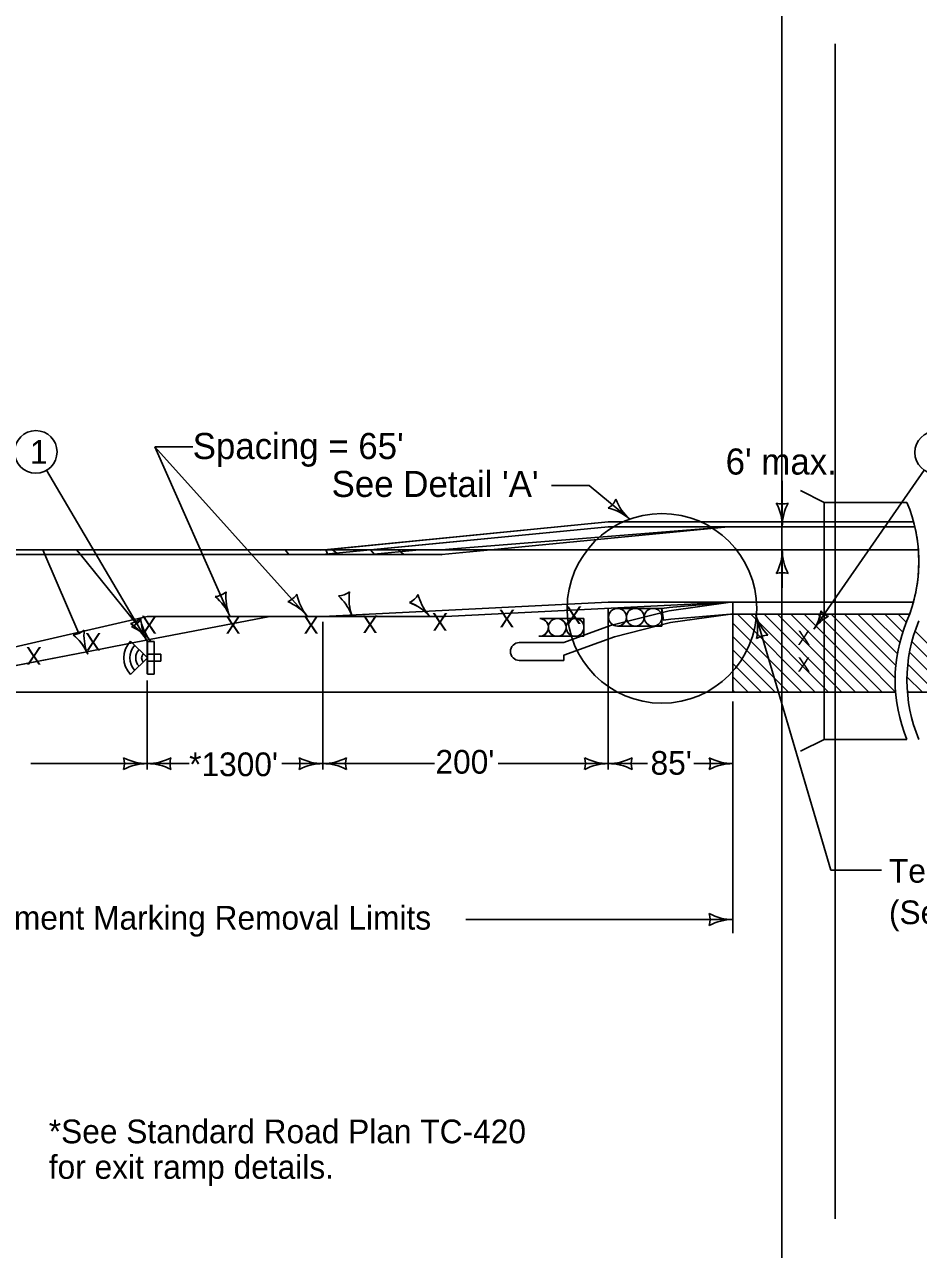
# Model space of a CAD drawing. Extents: x 10133 to 81668, y 4177 to 11018.
# Drawn here: x 29940 to 30695, y 8767 to 9800 of the extents above; entities that cross this region are included whole.
import ezdxf

# ---------------------------------------------------------------- set-up
doc = ezdxf.new("R2010")
doc.units = 0
for name, color, linetype in [('dsnNonPlotable', 7, 'Continuous'), ('dsnShtPlotShapeBatchPrint', 7, 'Continuous'), ('dsnStdDimension', 7, 'Continuous'), ('dsnStdLabel', 7, 'Continuous'), ('dsnStdLineWork', 7, 'Continuous'), ('dsnStdNote', 7, 'Continuous'), ('Level 1', 7, 'Continuous'), ('Level 12', 7, 'Continuous'), ('Level 2', 7, 'Continuous')]:
    doc.layers.add(name, color=color, linetype=linetype)

# ---------------------------------------------------------------- blocks, each defined once
blk = doc.blocks.new('LT')
at = {"layer": 'dsnNonPlotable'}
for centre, radius, start, end in [((-3.56, 0), 1.64, 342.2666, 17.7333), ((0, 4.25), 4.25, 241.9275, 270), ((0, -4.25), 4.25, 90, 118.0725)]:
    blk.add_arc(centre, radius, start, end, dxfattribs=at)

msp = doc.modelspace()

# ---------------------------------------------------------------- linework, layer by layer
at = {"layer": 'dsnNonPlotable'}
for p, q in [((30538.3, 9237.1), (30538.3, 9302.8)), ((30538.3, 9295.2), (30596.4, 9237.1)), ((30542, 9302.8), (30607.7, 9237.1)), ((30553.3, 9302.8), (30619, 9237.1)), ((30564.6, 9302.8), (30630.3, 9237.1)), ((30575.9, 9302.8), (30641.7, 9237.1)), ((30587.2, 9302.8), (30653, 9237.1)), ((30598.5, 9302.8), (30664.3, 9237.1)), ((30609.9, 9302.8), (30649.8, 9262.8)), ((30621.2, 9302.8), (30675.2, 9248.7)), ((30632.5, 9302.8), (30675.8, 9259.5)), ((30643.8, 9302.8), (30677.2, 9269.4)), ((30655.1, 9302.8), (30679.1, 9278.8)), ((30666.4, 9302.8), (30681.7, 9287.5)), ((30677.7, 9302.8), (30684.7, 9295.8)), ((30538.3, 9283.9), (30585.1, 9237.1)), ((30692, 9288.5), (30743.5, 9237.1)), ((30043.8, 9252.4), (30043.8, 9279.9)), ((30049.5, 9279.7), (30049.5, 9252.2)), ((30538.3, 9272.6), (30573.8, 9237.1)), ((30689.4, 9279.8), (30732.2, 9237.1)), ((30649.8, 9262.8), (30675.6, 9237.1)), ((30687.3, 9270.6), (30720.8, 9237.1)), ((30538.3, 9261.2), (30562.5, 9237.1)), ((30685.9, 9260.7), (30709.5, 9237.1)), ((30538.3, 9249.9), (30551.1, 9237.1)), ((30685.2, 9250), (30698.2, 9237.1)), ((30538.3, 9238.6), (30539.8, 9237.1)), ((30649, 9241), (30653, 9237.1)), ((30685.5, 9238.5), (30686.9, 9237.1))]:
    msp.add_line(p, q, dxfattribs=at)
for points in [[(30043.9, 9252.2), (30043.9, 9279.7), (30049.5, 9279.7), (30049.5, 9252.2)], [(30043.9, 9268.9), (30043.9, 9263.2), (30049.5, 9263.2), (30049.5, 9268.9)], [(30049.5, 9263.2), (30049.5, 9268.9), (30055.1, 9268.9), (30055.1, 9263.2)]]:
    msp.add_lwpolyline(points, close=True, dxfattribs=at)
for centre, radius in [((30478.3, 9307.7), 80), ((30440.8, 9300.2), 7.5), ((30455.8, 9300.2), 7.5), ((30470.8, 9300.2), 7.5)]:
    msp.add_circle(centre, radius, dxfattribs=at)
at = {"layer": 'dsnShtPlotShapeBatchPrint'}
for p, q in [((30579.5, 9884), (30579.5, 8414)), ((30624.5, 9784), (30624.5, 8792.5))]:
    msp.add_line(p, q, dxfattribs=at)
at = {"layer": 'dsnStdDimension'}
for p, q in [((30190.2, 9356.9), (30433, 9380.6)), ((30194.5, 9357.1), (30433, 9380.6)), ((30433, 9376.6), (30232.5, 9357.1)), ((30232.5, 9357.1), (30433, 9376.6)), ((30534.2, 9376.6), (30298.7, 9357.7)), ((30333.7, 9357.1), (30534.2, 9376.6)), ((30433, 9380.6), (30690.8, 9380.6)), ((30433, 9380.6), (30579.7, 9380.6)), ((30579.9, 9376.6), (30433, 9376.6)), ((30433, 9376.6), (30570, 9376.6)), ((30570, 9376.6), (30579.9, 9376.6)), ((30587.9, 9376.6), (30579.9, 9376.6)), ((30579.9, 9376.6), (30587.9, 9376.6)), ((30580, 9380.6), (30615.2, 9380.6)), ((30615.2, 9376.6), (30587.9, 9376.6)), ((30587.9, 9376.6), (30615.2, 9376.6)), ((30615.2, 9380.6), (30615.2, 9376.6)), ((30615.2, 9380.6), (30615.2, 9376.6)), ((30691.8, 9376.6), (30615.2, 9376.6)), ((30615.2, 9376.6), (30615.2, 9357.1)), ((30615.2, 9376.6), (30615.2, 9357.1)), ((30615.2, 9376.6), (30691.8, 9376.6)), ((30664.5, 9380.6), (30690.9, 9380.6)), ((28165.7, 9357.1), (30292.4, 9357.1)), ((29955.6, 9357.1), (28165.7, 9357.1)), ((29984.1, 9357.1), (29955.6, 9357.1)), ((29955.6, 9357.1), (29957.3, 9353.1)), ((29957.3, 9353.1), (29955.6, 9357.1)), ((30194.5, 9357.1), (29984.1, 9357.1)), ((29984.1, 9357.1), (29987.3, 9353.1)), ((29987.3, 9353.1), (29984.1, 9357.1)), ((30163.2, 9353.1), (30160.3, 9357.1)), ((30160.3, 9357.1), (30200.1, 9357.1)), ((30196.1, 9353.1), (30194.5, 9357.1)), ((30232.5, 9357.1), (30194.5, 9357.1)), ((30255.6, 9357.1), (30194.5, 9357.1)), ((30194.5, 9357.1), (30196.1, 9353.1)), ((30200.1, 9357.1), (30205.1, 9353.1)), ((30205.1, 9353.1), (30200.1, 9357.1)), ((30200.1, 9357.1), (30231.6, 9357.1)), ((30231.6, 9357.1), (30273.5, 9357.1)), ((30232.1, 9357.1), (30235.7, 9353.1)), ((30273.5, 9357.1), (30232.2, 9353.1)), ((30517.2, 9357.1), (30232.5, 9357.1)), ((30260.4, 9353.1), (30255.6, 9357.1)), ((30298.7, 9357.7), (30292.4, 9357.1)), ((30292.4, 9357.1), (30333.7, 9357.1)), ((30292.6, 9353.1), (30333.7, 9357.1)), ((30517.2, 9357.1), (30333.7, 9357.1)), ((30569, 9357.1), (30517.2, 9357.1)), ((30579.9, 9357.1), (30569, 9357.1)), ((30579.9, 9337.8), (30579.9, 9357.1)), ((30615.2, 9357.1), (30694.8, 9357.1)), ((30694.8, 9357.1), (30615.2, 9357.1)), ((30615.2, 9357.1), (30615.2, 9312.8)), ((30615.2, 9312.8), (30615.2, 9357.1)), ((28161.7, 9353.1), (29957.3, 9353.1)), ((29957.3, 9353.1), (29379, 9353.1)), ((29957.3, 9353.1), (29987.3, 9353.1)), ((29985.9, 9286.5), (29957.3, 9353.1)), ((29987.3, 9353.1), (29957.3, 9353.1)), ((29957.3, 9353.1), (29985.9, 9286.5)), ((29987.3, 9353.1), (30196.1, 9353.1)), ((30196.1, 9353.1), (29987.3, 9353.1)), ((29987.3, 9353.1), (30034.6, 9294.7)), ((30034.6, 9294.7), (29987.3, 9353.1)), ((30205.1, 9353.1), (30163.2, 9353.1)), ((30196.1, 9353.1), (30260.4, 9353.1)), ((30235.7, 9353.1), (30196.1, 9353.1)), ((30232.2, 9353.1), (30205.1, 9353.1)), ((30536.3, 9312.8), (30295.3, 9300.8)), ((30295.3, 9300.8), (30536.3, 9312.8)), ((30479.6, 9297.8), (30478.3, 9307.7)), ((30538.3, 9312.9), (30536.3, 9312.8)), ((30536.3, 9312.8), (30690.6, 9312.8)), ((30536.3, 9312.8), (30615.2, 9312.8)), ((30538.3, 9302.8), (30538.3, 9312.9)), ((30615.2, 9312.8), (30690.6, 9312.8)), ((30147.1, 9300.8), (30045.5, 9281.3)), ((30045.5, 9281.3), (30147.1, 9300.8)), ((30262.5, 9300.8), (30147.1, 9300.8)), ((30147.1, 9300.8), (30295.3, 9300.8)), ((30215.9, 9303.2), (30216.7, 9301.1)), ((30295.3, 9300.8), (30262.5, 9300.8)), ((30262.7, 9300.5), (30262.5, 9300.8)), ((30280.5, 9303), (30282.2, 9301.1)), ((30282.2, 9301.1), (30280.5, 9303)), ((30375.3, 9299.1), (30389.9, 9299.1)), ((30390.3, 9299.1), (30405.3, 9299.1)), ((30405.3, 9299.1), (30412.5, 9299.1)), ((30412.5, 9299.1), (30412.5, 9291.6)), ((30687.4, 9302.8), (30536.3, 9302.8)), ((30538.3, 9237.1), (30538.3, 9302.8)), ((30389.6, 9284.1), (30374.9, 9284.1)), ((30404.6, 9284.1), (30389.6, 9284.1)), ((30412.5, 9284.1), (30404.6, 9284.1)), ((30412.5, 9291.2), (30412.5, 9284.1)), ((30045.5, 9281.3), (29992.7, 9271.1)), ((29992.7, 9271.1), (30045.5, 9281.3)), ((30046.7, 9279.8), (30046.3, 9280.3)), ((30357.9, 9278.8), (30395.4, 9278.8)), ((30395.4, 9278.8), (30357.9, 9278.8)), ((29836.4, 9241.1), (29992.6, 9271.1)), ((29992.6, 9271.1), (29836.4, 9241.1)), ((30395.4, 9263.8), (30357.9, 9263.8)), ((30357.9, 9263.8), (30395.4, 9263.8)), ((30395.4, 9263.8), (30395.4, 9268.1)), ((28165.7, 9237.1), (30497.9, 9237.1)), ((29595.5, 9237.1), (30426.1, 9237.1)), ((30426.1, 9237.1), (30675.6, 9237.1)), ((30856, 9237.1), (30685.6, 9237.1))]:
    msp.add_line(p, q, dxfattribs=at)
for points in [[(30690.8, 9380.6), (30664.5, 9380.6), (30615.2, 9380.6)], [(30690.8, 9380.6), (30690.8, 9380.6)], [(30333.7, 9357.1), (30292.4, 9357.1), (30232.1, 9357.1)], [(30333.7, 9357.1), (30292.6, 9353.1), (30291.6, 9353)], [(30615.2, 9357.1), (30587.9, 9357.1), (30579.9, 9357.1), (30569, 9357.1), (30517.2, 9357.1)], [(30615.2, 9357.1), (30587.9, 9357.1), (30579.9, 9357.1)], [(30235.7, 9353.1), (30291.6, 9353.1), (30292.6, 9353.1)], [(30291.6, 9353.1), (30287.3, 9353.1), (30235.7, 9353.1)], [(30291.6, 9353), (30291.6, 9353.1)], [(30395.4, 9278.8), (30434.9, 9293.1), (30484.4, 9305.5), (30536.3, 9312.8)], [(30536.3, 9312.8), (30484.4, 9305.5), (30434.9, 9293.1), (30395.4, 9278.8)], [(30478.3, 9307.7), (30484.4, 9308.5), (30536, 9312.8), (30536.3, 9312.8)], [(30536.3, 9312.8), (30536.3, 9312.8)], [(30216.7, 9301.1), (30216.7, 9301.1), (30215.9, 9303.2)], [(30216.7, 9301.1), (30216.7, 9301.1)], [(30282.2, 9301.1), (30282.2, 9301.1)], [(30282.2, 9301.1), (30282.2, 9301.1)], [(30375.3, 9299.1), (30375.3, 9299.1)], [(30390.3, 9299.1), (30390.3, 9299.1)], [(30538.3, 9302.8), (30536.3, 9302.8), (30485.6, 9295.7), (30438.3, 9283.7), (30395.4, 9268.1)], [(30395.4, 9268.1), (30438.3, 9283.7), (30485.6, 9295.7), (30536.3, 9302.8), (30538.3, 9302.8)], [(30405.3, 9299.1), (30405.3, 9299.1)], [(30405.3, 9299.1), (30405.3, 9299.1)], [(30536.3, 9302.8), (30485.7, 9298.6), (30479.6, 9297.8)], [(30382.4, 9291.2), (30382.5, 9291.2)], [(30389.6, 9284.1), (30389.6, 9284.1)], [(30389.6, 9284.1), (30389.6, 9284.1)], [(30397.4, 9291.2), (30397.5, 9291.2)], [(30404.6, 9284.1), (30404.6, 9284.1)], [(30404.6, 9284.1), (30404.6, 9284.1)], [(30412.4, 9291.2), (30412.5, 9291.2)], [(30045.5, 9281.2), (30045.6, 9281.3)], [(29993.5, 9268.9), (29993.5, 9268.9), (29993.2, 9269.8)], [(29993.2, 9269.7), (29993.2, 9269.8)], [(30395.4, 9268.1), (30395.4, 9268.1), (30395.4, 9263.8)], [(30426.1, 9237.1), (30497.9, 9237.1), (30538.3, 9237.1)]]:
    msp.add_lwpolyline(points, dxfattribs=at)
for centre, radius, start, end in [((30537.4, 9376.6), 42.5, 0, 5.4005), ((30622.4, 9376.6), 42.5, 174.5995, 179.9824), ((30537.4, 9376.6), 42.5, 0, 0.0176), ((30565.2, 9347.1), 130, 13.1184, 14.9371), ((30565.2, 9347.1), 130, 4.4117, 13.1184), ((30537.4, 9357.1), 42.5, 331.9275, 0), ((30565.2, 9347.1), 130, 344.7177, 4.4117), ((30579.9, 9321.4), 16.4, 90, 107.7334), ((30204.4, 9334.6), 16.4, 272.4117, 307.8784), ((30204.4, 9334.6), 16.4, 272.4117, 307.8784), ((30176.8, 9286.5), 42.5, 23.0899, 48.2175), ((30176.8, 9286.5), 42.5, 23.0899, 48.2175), ((30256.6, 9315.8), 42.5, 172.0726, 200.1275), ((30256.6, 9315.8), 42.5, 172.0726, 200.1275), ((30258.3, 9327.6), 16.4, 294.2304, 329.6971), ((30258.4, 9327.6), 16.4, 294.2304, 329.6971), ((30313.8, 9329.5), 42.5, 193.8912, 218.5415), ((30313.8, 9329.5), 42.5, 193.8912, 218.5415), ((30250.6, 9272.7), 42.5, 41.9813, 70.0362), ((30250.6, 9272.6), 42.5, 41.9813, 70.0362), ((30565.2, 9347.1), 130, 340.0928, 344.7177), ((30024.5, 9307.6), 16.4, 290.8549, 326.3216), ((30024.5, 9307.6), 16.4, 290.8549, 308.0905), ((30024.5, 9307.6), 16.4, 308.0905, 326.3216), ((30079.9, 9306.3), 42.5, 190.5158, 216.0585), ((30079.9, 9306.3), 42.5, 190.5158, 216.0585), ((30176.8, 9286.5), 42.5, 20.1451, 20.1627), ((30297.1, 9325.5), 42.5, 215.5389, 216.0818), ((30228.4, 9275.4), 42.5, 36.0994, 36.117), ((30297.1, 9325.5), 42.5, 216.0989, 216.0994), ((30313.8, 9329.5), 42.5, 221.9461, 221.9637), ((30374.9, 9291.6), 7.55, 3.3189, 86.8597), ((30374.9, 9291.6), 7.5, 42.0293, 86.9975), ((30374.9, 9291.6), 7.55, 3.3337, 42.1724), ((30389.9, 9291.6), 7.5, 267, 266.9552), ((30389.9, 9291.6), 7.5, 90.3225, 176.9869), ((30389.9, 9291.6), 7.55, 3.323, 86.8556), ((30389.9, 9291.6), 7.5, 40.9459, 87.0002), ((30389.9, 9291.6), 7.55, 3.4004, 41.098), ((30405, 9291.6), 7.5, 86.9958, 177.0042), ((30405, 9291.6), 7.5, 86.9975, 176.9187), ((30405, 9291.6), 7.5, 356.9998, 87.0002), ((30405, 9291.6), 7.5, 0, 86.9975), ((29979.8, 9301.8), 16.4, 274.9287, 310.3954), ((29979.8, 9301.8), 16.4, 274.9287, 291.9208), ((29954.3, 9252.5), 42.5, 25.9041, 50.7345), ((29954.3, 9252.5), 42.5, 23.928, 50.7345), ((29979.8, 9301.8), 16.4, 291.9208, 310.3954), ((30032.8, 9285.3), 42.5, 174.5895, 199.4578), ((30032.8, 9285.3), 42.5, 174.5895, 199.4578), ((30013.5, 9253.3), 42.5, 41.1781, 66.6607), ((30013.5, 9253.3), 42.5, 41.1781, 66.6607), ((30374.9, 9291.6), 7.5, 267.0001, 356.9999), ((30374.9, 9291.6), 7.5, 270, 357.0043), ((30389.9, 9291.6), 7.5, 182.9876, 266.9583), ((30389.9, 9291.6), 7.5, 267.0031, 357.0043), ((30405, 9291.6), 7.5, 177.006, 266.994), ((30405, 9291.6), 7.5, 182.9876, 267.0031), ((30404.9, 9291.6), 7.51, 267.1005, 356.8995), ((30405, 9291.6), 7.5, 267.0031, 357.0041), ((30079.9, 9306.3), 42.5, 216.0585, 218.5706), ((30013.5, 9253.3), 42.5, 39.4385, 41.1781), ((30013.5, 9253.3), 42.5, 38.5882, 38.6058), ((30079.9, 9306.3), 42.5, 218.5875, 218.5882), ((30357.9, 9271.3), 7.5, 90, 270), ((30357.9, 9271.3), 7.5, 90, 270), ((29954.3, 9252.5), 42.5, 23.928, 25.9041), ((30032.8, 9285.3), 42.5, 199.4578, 202.6444), ((30032.8, 9285.3), 42.5, 199.4578, 201.3966), ((29954.3, 9252.5), 42.5, 22.662, 22.6796)]:
    msp.add_arc(centre, radius, start, end, dxfattribs=at)
at = {"layer": 'dsnStdLabel'}
for p, q in [((30615.2, 9397.1), (30595.2, 9407.1)), ((30191.3, 9353.1), (30433, 9376.6)), ((30433, 9376.6), (30691.8, 9376.6)), ((30534.2, 9376.6), (30691.8, 9376.6)), ((30194.5, 9357.1), (30517.2, 9357.1)), ((30517.2, 9357.1), (30694.8, 9357.1)), ((30192, 9300.8), (30433, 9312.8)), ((30433, 9312.8), (30536.3, 9312.8)), ((30690.6, 9312.8), (30664.3, 9312.8)), ((29785, 9241.1), (30043.8, 9300.8)), ((30043.8, 9300.8), (30192, 9300.8)), ((30661.1, 9302.8), (30687.4, 9302.8)), ((30615.2, 9197.1), (30595.2, 9187.1))]:
    msp.add_line(p, q, dxfattribs=at)
for points in [[(30685.2, 9197.1), (30615.2, 9197.1), (30615.2, 9397.1), (30685.2, 9397.1)], [(28161.7, 9353.1), (30191.3, 9353.1)], [(30478.3, 9307.7), (30484.4, 9308.5), (30536.3, 9312.8)], [(30478.3, 9307.7), (30479.6, 9297.8), (30479.6, 9297.8)], [(30690.6, 9312.8), (30536.3, 9312.8)], [(30479.6, 9297.8), (30485.7, 9298.6), (30536.3, 9302.8)], [(30536.3, 9302.8), (30687.4, 9302.8)]]:
    msp.add_lwpolyline(points, dxfattribs=at)
for centre, start, end in [((30565.2, 9347.1), 337.3801, 22.6199), ((30805.2, 9247.1), 157.3801, 202.6199), ((30815.2, 9247.1), 157.3801, 202.6199)]:
    msp.add_arc(centre, 130, start, end, dxfattribs=at)
at = {"layer": 'dsnStdLineWork'}
for p, q in [((30478.3, 9307.7), (30440.8, 9307.7)), ((30478.3, 9292.7), (30478.3, 9307.7)), ((30440.8, 9292.7), (30478.3, 9292.7)), ((30029.7, 9280.1), (30043.9, 9265.9)), ((30049.5, 9279.7), (30043.9, 9279.7)), ((30043.9, 9265.9), (30029.7, 9251.8)), ((30049.5, 9252.2), (30043.9, 9252.2))]:
    msp.add_line(p, q, dxfattribs=at)
for centre in [(30440.8, 9300.2), (30440.8, 9300.2), (30455.8, 9300.2), (30455.8, 9300.2), (30470.8, 9300.2), (30470.8, 9300.2)]:
    msp.add_circle(centre, 7.5, dxfattribs=at)
for radius, start, end in [(20.3, 135.88, 224.0313), (15.3, 136.1665, 223.7159), (10.3, 136.7294, 223.0963), (5.32, 138.7005, 221.2995)]:
    msp.add_arc((30044.3, 9265.9), radius, start, end, dxfattribs=at)
at = {"layer": 'dsnStdNote'}
for p, q in [((30050.1, 9444.1), (30082.1, 9444.1)), ((30113.4, 9301.1), (30050.1, 9444.1)), ((30178.9, 9301.1), (30050.1, 9444.1)), ((30043.8, 9279.9), (29958.7, 9424.2)), ((30606.6, 9290.1), (30699.6, 9424.4)), ((30385, 9411.3), (30417, 9411.3)), ((30451.2, 9382.9), (30417, 9411.3)), ((30579.9, 9415.3), (30579.9, 9376.6)), ((30570, 9376.6), (30587.9, 9376.6)), ((30569, 9357.1), (30587.9, 9357.1)), ((30579.9, 9325.1), (30579.9, 9357.1)), ((30433, 9307.9), (30433, 9171.8)), ((30192, 9296.4), (30192, 9171.8)), ((30557.4, 9302.8), (30620.9, 9086.8)), ((30043.8, 9246.7), (30043.8, 9171.8)), ((30538.3, 9229.1), (30538.3, 9033.7)), ((30045.5, 9176.7), (29945.5, 9176.7)), ((29988.2, 9176.7), (30079.1, 9176.7)), ((30286.4, 9176.7), (30157.3, 9176.7)), ((30285.8, 9176.7), (30192, 9176.7)), ((30433.1, 9176.7), (30339.9, 9176.7)), ((30466.1, 9176.7), (30433.1, 9176.7)), ((30538.3, 9176.7), (30505.3, 9176.7)), ((30663.7, 9086.8), (30620.9, 9086.8)), ((30312.6, 9045.1), (30538.3, 9045.1))]:
    msp.add_line(p, q, dxfattribs=at)
for centre, radius, start, end in [((30424.4, 9406.3), 16.4, 301.2201, 336.6868), ((30479.1, 9415), 42.5, 200.881, 228.9535), ((30579.9, 9412.2), 16.4, 252.2666, 287.7334), ((30537.4, 9376.6), 42.5, 0, 28.0725), ((30622.4, 9376.6), 42.5, 151.9275, 180), ((30423.3, 9350.9), 42.5, 48.9535, 77.026), ((30537.4, 9357.1), 42.5, 331.9275, 0), ((30622.4, 9357.1), 42.5, 180, 208.0725), ((30579.9, 9321.4), 16.4, 72.2666, 107.7334), ((30099.6, 9334), 16.4, 274.8945, 310.3612), ((30074.1, 9284.8), 42.5, 22.6279, 50.7004), ((30152.6, 9317.5), 42.5, 174.5554, 202.6279), ((30156.3, 9328.6), 16.4, 291.6303, 327.097), ((30211.7, 9328), 42.5, 191.2912, 219.3636), ((30146, 9274.1), 42.5, 39.3636, 67.4361), ((30026.3, 9311), 16.4, 281.5553, 317.0221), ((30006.7, 9259.1), 42.5, 29.2887, 57.3612), ((30080.8, 9300.7), 42.5, 181.2162, 209.2887), ((30516.6, 9290.8), 42.5, 348.3144, 16.3869), ((30598.1, 9314.8), 42.5, 196.3869, 224.4594), ((30567.4, 9268.6), 16.4, 88.6536, 124.1203), ((30008.1, 9176.7), 16.4, 342.2666, 17.7334), ((30043.8, 9219.2), 42.5, 241.9275, 270), ((30043.8, 9219.2), 42.5, 270, 298.0725), ((30079.4, 9176.7), 16.4, 162.2666, 197.7334), ((30156.3, 9176.7), 16.4, 342.2666, 17.7334), ((30192, 9219.2), 42.5, 241.9275, 270), ((30192, 9219.2), 42.5, 270, 298.0725), ((30227.6, 9176.7), 16.4, 162.2666, 197.7334), ((30397.4, 9176.7), 16.4, 342.2667, 17.7334), ((30433.1, 9219.2), 42.5, 241.9275, 270), ((30433.1, 9219.2), 42.5, 270, 298.0725), ((30468.7, 9176.7), 16.4, 162.2666, 197.7334), ((30502.7, 9176.7), 16.4, 342.2667, 17.7334), ((30538.3, 9219.2), 42.5, 241.9275, 270), ((30043.8, 9134.2), 42.5, 90, 118.0725), ((30043.8, 9134.2), 42.5, 61.9275, 90), ((30192, 9134.2), 42.5, 90, 118.0725), ((30192, 9134.2), 42.5, 61.9275, 90), ((30433.1, 9134.2), 42.5, 90, 118.0725), ((30433.1, 9134.2), 42.5, 61.9275, 90), ((30538.3, 9134.2), 42.5, 90, 118.0725), ((30502.6, 9045.1), 16.4, 342.2667, 17.7334), ((30538.3, 9087.6), 42.5, 241.9275, 270), ((30538.3, 9002.6), 42.5, 90, 118.0725)]:
    msp.add_arc(centre, radius, start, end, dxfattribs=at)
at = {"layer": 'Level 12'}
msp.add_circle((29949.6, 9439.7), 18, dxfattribs=at)
at = {"layer": 'Level 2'}
msp.add_circle((30709.9, 9439.2), 18, dxfattribs=at)

# ---------------------------------------------------------------- block references
at = {"layer": 'dsnStdNote', "xscale": 7.999600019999, "yscale": 7.999200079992, "rotation": -124.70293665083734}
msp.add_blockref('LT', (30606.6, 9290.1), dxfattribs=at)

# ---------------------------------------------------------------- texts
at = {"layer": 'dsnNonPlotable'}
for p in [(30297.6, 9303.8), (30354.1, 9306.6), (30410.7, 9309.4), (30052.2, 9301.4), (30122.9, 9301.4), (30188.8, 9301.4), (30238.6, 9301.9), (30004.8, 9286.9), (29954.7, 9275.2)]:
    msp.add_text('X', height=15, rotation=180, dxfattribs=at).set_placement(p)
for p in [(30592.8, 9276.9), (30592.8, 9254.3)]:
    msp.add_text('X', height=12, dxfattribs=at).set_placement(p)
at = {"layer": 'dsnStdNote'}
for s, height, p in [("Spacing = 65'", 22, (30082.1, 9433.7)), ("6' max.", 22, (30532.1, 9420.6)), ("See Detail 'A'", 22, (30199.4, 9401.7)), ("*1300'", 20, (30079.1, 9166.1)), ("200'", 20, (30287.1, 9168.2)), ("85'", 20, (30468.7, 9167.3)), ('Temporary Barrier Rail', 20, (30670, 9076.2)), ('Pavement Marking Removal Limits', 20, (29870.2, 9036.6)), ('(See Typical 8210)', 20, (30670, 9041.2))]:
    msp.add_text(s, height=height, dxfattribs=at).set_placement(p)
at = {"layer": 'Level 1'}
for s, p in [('*See Standard Road Plan TC-420', (29960.6, 8856.3)), ('for exit ramp details.', (29960.6, 8826.3))]:
    msp.add_text(s, height=20, dxfattribs=at).set_placement(p)
at = {"layer": 'Level 12'}
msp.add_text('1', height=20, dxfattribs=at).set_placement((29944.8, 9429.7))

doc.saveas('drawing.dxf')
